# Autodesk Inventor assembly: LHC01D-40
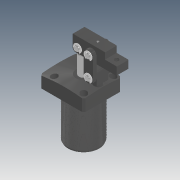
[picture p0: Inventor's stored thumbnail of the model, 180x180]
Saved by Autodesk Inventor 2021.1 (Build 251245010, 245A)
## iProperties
Created: 2019-04
Part Number: LHC01D-40
Description: STEP AP214
Document SubType Name: Assembly
Designer: user
Sending System: SolidWorks 2016
Preprocessor: SwSTEP 2.0
Title: LHC01D-40.STEP
Revision Number: ÈÎºÎ
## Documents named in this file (12)
- D:\Vault_2016\Projekty\Clamptek\Hydraulic\Dociski Hydrauliczne\Dźwigniowe\LHC01D\Inventor\LHC01D-40\LHC01D-40.iam
- D:\Vault_2016\Projekty\Clamptek\Hydraulic\Dociski Hydrauliczne\Dźwigniowe\LHC01D\Inventor\LHC01D-40\LHC01D-40-07.ipt
- D:\Vault_2016\Projekty\Clamptek\Hydraulic\Dociski Hydrauliczne\Dźwigniowe\LHC01D\Inventor\LHC01D-40\LHC01D40»îÈû¸Ë.ipt
- D:\Vault_2016\Projekty\Clamptek\Hydraulic\Dociski Hydrauliczne\Dźwigniowe\LHC01D\Inventor\LHC01D-40\CPLCU-40ZCK.ipt
- D:\Vault_2016\Projekty\Clamptek\Hydraulic\Dociski Hydrauliczne\Dźwigniowe\LHC01D\Inventor\LHC01D-40\CPLCU-40YB.ipt
- D:\Vault_2016\Projekty\Clamptek\Hydraulic\Dociski Hydrauliczne\Dźwigniowe\LHC01D\Inventor\LHC01D-40\CPLCU-40LG.ipt
- D:\Vault_2016\Projekty\Clamptek\Hydraulic\Dociski Hydrauliczne\Dźwigniowe\LHC01D\Inventor\LHC01D-40\CPLCU-40DX.ipt
- D:\Vault_2016\Projekty\Clamptek\Hydraulic\Dociski Hydrauliczne\Dźwigniowe\LHC01D\Inventor\LHC01D-40\CPLCU-40X.ipt
- D:\Vault_2016\Projekty\Clamptek\Hydraulic\Dociski Hydrauliczne\Dźwigniowe\LHC01D\Inventor\LHC01D-40\LHC01D-40-05.ipt
- D:\Vault_2016\Projekty\Clamptek\Hydraulic\Dociski Hydrauliczne\Dźwigniowe\LHC01D\Inventor\LHC01D-40\LHC01D-40-08.ipt
- D:\Vault_2016\Projekty\Clamptek\Hydraulic\Dociski Hydrauliczne\Dźwigniowe\LHC01D\Inventor\LHC01D-40\M4ningjin_4.ipt
- D:\Vault_2016\Projekty\Clamptek\Hydraulic\Dociski Hydrauliczne\Dźwigniowe\LHC01D\Inventor\LHC01D-40\¶ÂÍ·_7.ipt
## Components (24 placed, 24 different names)
1. LHC01D-40-07_1
2. LHC01D40»îÈû¸Ë_2
3. CPLCU-40ZCK_3
4. CPLCU-40YB_4
5. CPLCU-40LG_5
6. CPLCU-40LG_6
7. CPLCU-40DX_7
8. CPLCU-40X_8
9. CPLCU-40X_9
10. LHC01D-40-05_10
11. LHC01D-40-05_11
12. LHC01D-40-05_12
13. LHC01D-40-05_13
14. LHC01D-40-05_14
15. LHC01D-40-05_15
16. LHC01D-40-08_16
17. LHC01D-40-08_17
18. LHC01D-40-08_18
19. LHC01D-40-08_19
20. LHC01D-40-08_20
21. LHC01D-40-08_21
22. M4ningjin_4_22
23. ¶ÂÍ·_7_23
24. ¶ÂÍ·_7_24
